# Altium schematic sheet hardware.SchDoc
size 431 x 279 mm; Date: Not shown in title block; ApprovedBy: Not shown in title block; CheckedBy: Not shown in title block; Author: Not shown in title block; CompanyName: Not shown in title block; Engineer: Not shown in title block; Organization: Not shown in title block; Address1: Not shown in title block; Address2: Not shown in title block; Address3: Not shown in title block; Address4: Not shown in title block; DocumentNumber: 3; Revision: Use project parameter SCH_Rev; SheetNumber: 3; SheetTotal: 3; PageSetup: Record=PageOptions¦CenterHorizontal=True¦CenterVertical=True¦PrintScale=1.00¦XCorrection=1.00¦YCorrection=1.00¦PrintKind=0¦BorderSize=5000000¦LeftOffset=0¦BottomOffset=0¦Orientation=2¦PaperLength=1000¦PaperWidth=1000¦Scale=100¦PaperSource=15¦PrintQuality=600¦MediaType=1¦DitherType=10¦PaperKind=Letter¦PrintScaleMode=1
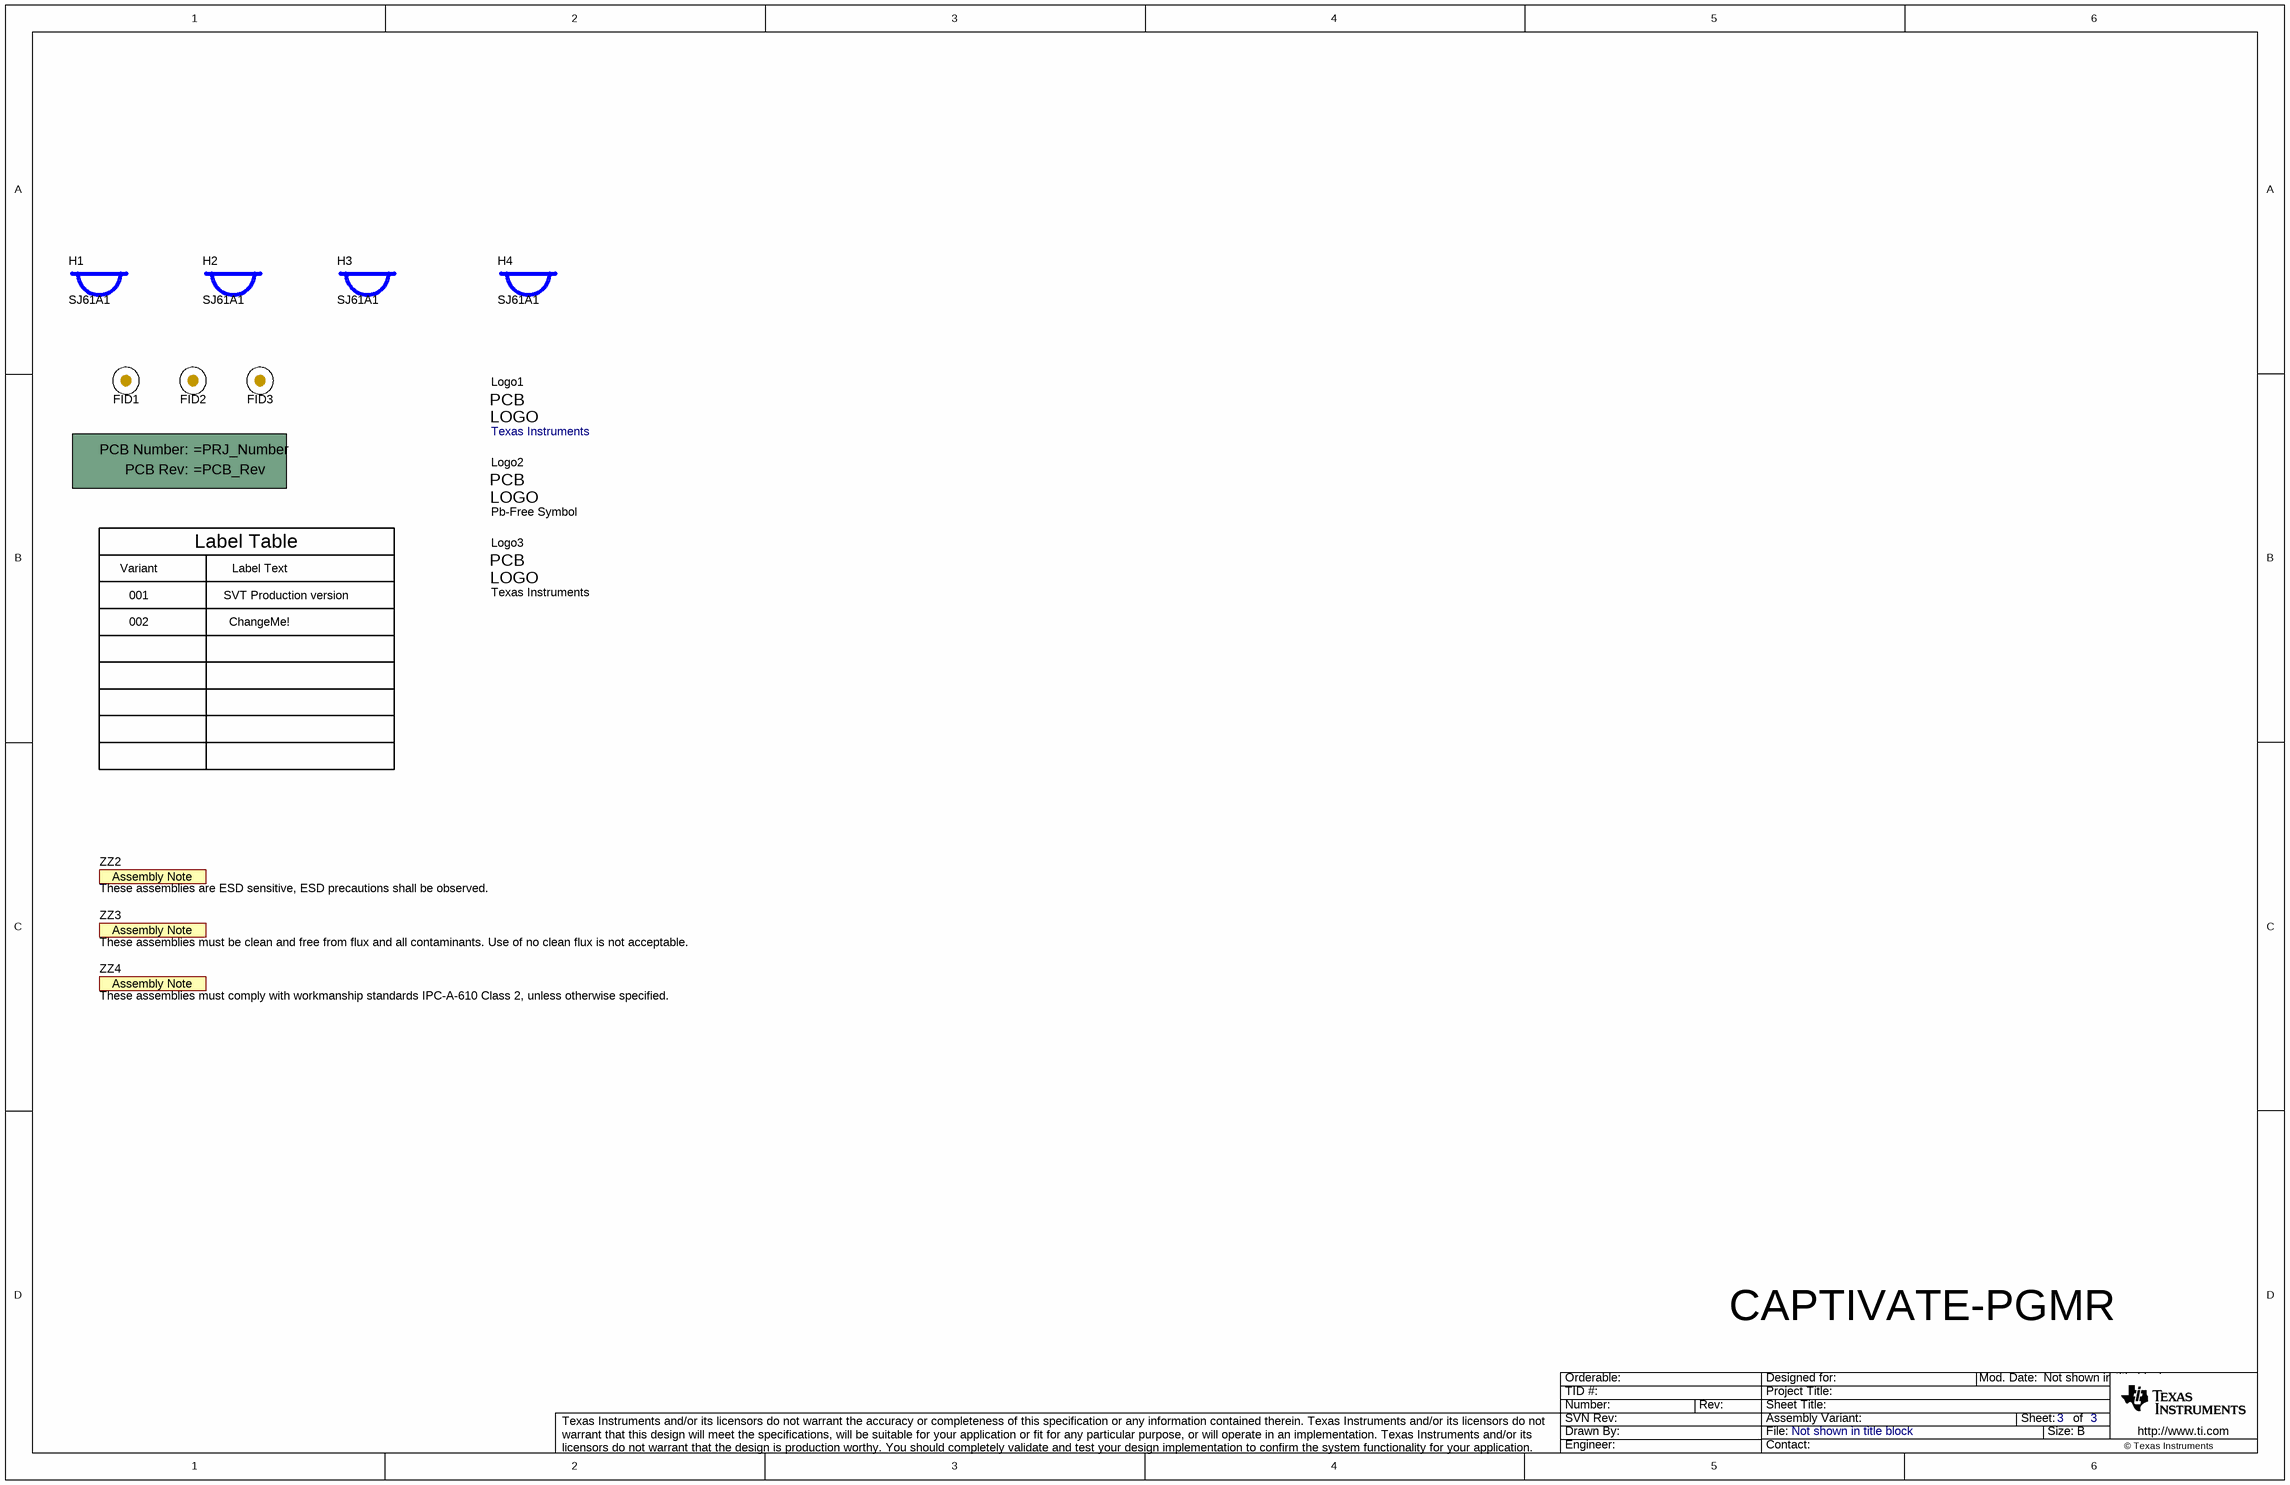
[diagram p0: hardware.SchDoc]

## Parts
!PCB1  Printed Circuit Board  (value not drawn)  (mechanical)
FID1  Fiducial  [Fiducial10-20]  (value not drawn)
FID2  Fiducial  [Fiducial10-20]  (value not drawn)
FID3  Fiducial  [Fiducial10-20]  (value not drawn)
H1  SJ61A1  [Bumpon_SJ61A1]
H2  SJ61A1  [Bumpon_SJ61A1]
H3  SJ61A1  [Bumpon_SJ61A1]
H4  SJ61A1  [Bumpon_SJ61A1]
Logo1  Texas Instruments  [TI_Stacked_Overlay_Small]  (no BOM)
Logo2  Pb-Free Symbol  [Pb-Free_Overlay_Small]  (no BOM)
Logo3  Texas Instruments  [TI_Symbol_Overlay_Small]  (no BOM)
ZZ2  These assemblies are ESD sensitive, ESD precautions shall be observed.  [AssemblyNote]  (no BOM)
ZZ3  These assemblies must be clean and free from flux and all contaminants. Use of no clean flux is not acceptable.  [AssemblyNote]  (no BOM)
ZZ4  These assemblies must comply with workmanship standards IPC-A-610 Class 2, unless otherwise specified.  [AssemblyNote]  (no BOM)

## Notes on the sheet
- Variant
- Label Table
- Label Text
- 001
- 002
- ChangeMe!
- SVT Production version
- CAPTIVATE-PGMR

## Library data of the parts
!PCB1 = PCB: Manufacturer: Any; SymbolCreator: a0412235
FID1-FID3 = Fiducial: Fiducial mark.  There is nothing to buy or mount.; SymbolCreator: codlsc
H1-H4 = SJ61A1: Bumpon, Cylindrical, 0.312 X 0.200, Black; Manufacturer: 3M; SymbolCreator: a0412235
Logo1 Logo3 = TI_Logo: Texas Instrument Corporate Signature; SymbolCreator: a0412235
Logo2 = Pb-Free: SymbolCreator: a0412235
ZZ2-ZZ4 = AssemblyNote: SymbolCreator: codlsc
